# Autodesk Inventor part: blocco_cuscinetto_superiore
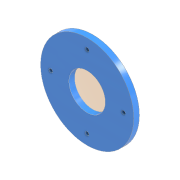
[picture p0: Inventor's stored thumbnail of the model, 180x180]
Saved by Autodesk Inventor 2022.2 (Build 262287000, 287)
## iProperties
Created: 2025-03
Part Number: blocco_cuscinetto_superiore
Material: Generico
Document SubType Name: Modeling
Designer: 18907419
Density: 1 g/cm^3
Appearance: Ciano
Author: 18907419
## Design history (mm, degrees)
sketch "Schizzo1"
  geometry: C1 r 21 at (41, 0) reference; C2 r 16 at (41, 0); C3 r 2.75 at (41, -32) reference; C4 r 2.75 at (73, 0) reference; C5 r 2.75 at (41, 32) reference; C6 r 2.75 at (9, 0) reference; 2 further points
  constraints: 1 centre point, 1 coincident, 1 horizontal alignment
  dimensions: "d0" = 32 diameter of C2
extrude "Estrusione1" new body sketch "Schizzo1" distance "d1" = 5; taper "d2" = 0 deg
node "Piano di lavoro1"
sketch "Schizzo2"
  geometry: L1 (0, 0)-(0, -32); 2 further points
  constraints: 2 end point, 1 coincident
  dimensions: "d3" = 32 distance of L1.start L1.end
hole "Foro1" sketch "Schizzo2" at (0, -32) diameter "d4" = 3.2; stored, may be unused: countersink angle "d8" = 82 deg, drill point angle "d10" = 0 deg; dims "d5" = 6, "d6" = 13, "d7" = 3.4, "d9" = 8
pattern_circular "Serie circolare1" dims angle "d12" = 360 deg
node "Solido1"
node "Riferimento1"
